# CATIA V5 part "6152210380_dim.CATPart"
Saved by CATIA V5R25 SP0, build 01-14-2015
Part number: 6152210380_dim
Source: made
Property "PROI_CREATED_ON": "12/17/2008 9:21:37 AM"
Property "BLANK_DRAWING": "--"
Property "DRAWN_BY": "FPA"
Property "FINISH": "--"
Property "HEAT_TREATMENT": "ASSIGN"
Property "MATERIAL": "ASSIGN"
Property "PROJECT": "--"
Property "PROTOTYPE_NO": "--"
Property "RELATED_DRAWING": "--"
Property "COMPLETE_MATERIAL": "ASSIGN-ASSIGN"
Property "DESCRIPTION": "Q-SHIELD 350-S"
Property "DRAWING_EXIST": "--"
Property "MANUFACTURER": "--"
Property "MANUFACTURER_2": "--"
Property "MANUFACTURER_REF": "--"
Property "TYPE_PART": "--"
Property "TODAY_DATE": "2021/06/09"
Property "PDMREV": "01.0"
Property "PDMRL": "Production"
Property "PROI_REVISION": "01"
Property "PROI_VERSION": "0"
Property "PROI_RELEASE": "Production"
Property "PTC_MODIFIED": false
Property "MFG_WP_MATERIAL": "ASSIGN"
Property "COMPANY_CODE": "---"
Property "DESCRIPTION_JP": "--"
Property "PQP_DOCUMENT": "--"
Property "GHOST": false
Property "NO_PART": false
Property "PTC_WM_ITERATION": "0"
Property "PTC_WM_VERSION": "01.0"
Property "PTC_WM_CREATED_ON": "09-Jun-21 09:10:23 AM"
Property "PTC_WM_MODIFIED_ON": "10-Jun-21 03:21:17 PM"
Property "PTC_WM_NAME": "6152210380_dim.prt"
Property "PTC_WM_NUMBER": "6152210380_DIM.PRT"
Property "PTC_WM_LIFECYCLE_STATE": "Production"
Property "PTC_WM_LIFECYCLE": "Design_Process"
Property "PTC_WM_REVISION": "01"
Property "PTC_WM_CREATED_BY": "Florian Pavageau (Grefpav) (Grefpav: CPD)"
Property "PTC_WM_MODIFIED_BY": "Florian Pavageau (Grefpav) (Grefpav: CPD)"
Property "PTC_ORGANIZATION_ID": "CPD"
Property "PTC_WM_LOCATION": "/Products/TORQUE MEASUREMENT SYSTEMS/A2010 - DELTAWRENCH GEN2/9-01-Dimensional D"
Property "PTC_WM_PART_NAME": "6152210380_dim.prt"
Property "PTC_WM_PART_NUMBER": "6152210380_DIM"
Property "PTC_WM_TEAM": "Default"
Property "EXPORT_CONTROL": "NULL"
Property "PTC_COMMON_NAME": "6152210380_dim.prt"
Property "PTC_MASTER_MATERIAL": "ASSIGN"
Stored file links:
  d:\ptc\Echange\temp\6152210380_dim.CATPart

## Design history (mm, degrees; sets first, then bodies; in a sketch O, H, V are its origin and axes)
AxisSystem1 "CS0": origin (0, 0, 0), X (1, 0, 0), Y (0, 1, 0), Z (0, 0, 1)
Set1
  DatumSurface1 "Sheet.1"
  DatumSurface2 "Sheet.2"
  DatumSurface3 "Sheet.3"
  DatumSurface4 "Sheet.4"
  DatumSurface5 "Sheet.5"
  DatumSurface6 "Sheet.6"
  DatumSurface7 "Sheet.7"
  DatumSurface8 "Sheet.8"
  DatumSurface9 "Sheet.9"
  DatumSurface10 "Sheet.10"
  DatumSurface11 "Sheet.11"
  DatumSurface12 "Sheet.12"
  DatumSurface13 "Sheet.13"
  DatumSurface14 "Sheet.14"
  DatumSurface15 "Sheet.15"
  DatumSurface16 "Sheet.16"
  DatumSurface17 "Sheet.17"
  DatumSurface18 "Sheet.18"
  DatumSurface19 "Sheet.19"
  DatumSurface20 "Sheet.20"
  DatumSurface21 "Sheet.21"
  DatumSurface22 "Sheet.22"
  DatumSurface23 "Sheet.23"
  DatumSurface24 "Sheet.24"
  DatumSurface25 "Sheet.25"
  DatumSurface26 "Sheet.26"
  DatumSurface27 "Sheet.27"
  DatumSurface28 "Sheet.28"
  DatumSurface29 "Sheet.29"
  DatumSurface30 "Sheet.30"
  DatumSurface31 "Sheet.31"
  DatumSurface32 "Sheet.32"
  DatumSurface33 "Sheet.33"
  DatumSurface34 "Sheet.34"
  DatumSurface35 "Sheet.35"
  DatumSurface36 "Sheet.36"
  DatumSurface37 "Sheet.37"
  DatumSurface38 "Sheet.38"
  DatumSurface39 "Sheet.39"
  DatumSurface40 "Sheet.40"
  DatumSurface41 "Sheet.41"
  DatumSurface42 "Sheet.42"
  DatumSurface43 "Sheet.43"
  DatumSurface44 "Sheet.44"
  DatumSurface45 "Sheet.45"
  DatumSurface46 "Sheet.46"
  DatumSurface47 "Sheet.47"
  DatumSurface48 "Sheet.48"
  DatumSurface49 "Sheet.49"
  DatumSurface50 "Sheet.50"
  DatumSurface51 "Sheet.51"
  DatumSurface52 "Sheet.52"
  DatumSurface53 "Sheet.53"
  DatumSurface54 "Sheet.54"
  DatumSurface55 "Sheet.55"
  DatumSurface56 "Sheet.56"
  DatumSurface57 "Sheet.57"
  DatumSurface58 "Sheet.58"
  DatumSurface59 "Sheet.59"
  DatumSurface60 "Sheet.60"
  DatumSurface61 "Sheet.61"
  DatumSurface62 "Sheet.62"
  DatumSurface63 "Sheet.63"
  DatumSurface64 "Sheet.64"
  DatumSurface65 "Sheet.65"
  DatumSurface66 "Sheet.66"
  DatumSurface67 "Sheet.67"
  DatumSurface68 "Sheet.68"
  DatumSurface69 "Sheet.69"
  DatumSurface70 "Sheet.70"
  DatumSurface71 "Sheet.71"
  DatumSurface72 "Sheet.72"
  DatumSurface73 "Sheet.73"
  DatumSurface74 "Sheet.74"
  DatumSurface75 "Sheet.75"
  DatumSurface76 "Sheet.76"
  DatumSurface77 "Sheet.77"
  DatumSurface78 "Sheet.78"
  DatumSurface79 "Sheet.79"
  DatumSurface80 "Sheet.80"
  DatumSurface81 "Sheet.81"
  DatumSurface82 "Sheet.82"
  DatumSurface83 "Sheet.83"
  DatumSurface84 "Sheet.84"
  DatumSurface85 "Sheet.85"
  DatumSurface86 "Sheet.86"
  DatumSurface87 "Sheet.87"
  DatumSurface88 "Sheet.88"
  DatumSurface89 "Sheet.89"
  DatumSurface90 "Sheet.90"
  DatumSurface91 "Sheet.91"
  DatumSurface92 "Sheet.92"
  DatumSurface93 "Sheet.93"
  DatumSurface94 "Sheet.94"
  DatumSurface95 "Sheet.95"
  DatumSurface96 "Sheet.96"
  DatumSurface97 "Sheet.97"
  DatumSurface98 "Sheet.98"
  DatumSurface99 "Sheet.99"
  DatumSurface100 "Sheet.100"
  DatumSurface101 "Sheet.101"
  DatumSurface102 "Sheet.102"
  DatumSurface103 "Sheet.103"
  DatumSurface104 "Sheet.104"
  DatumSurface105 "Sheet.105"
  DatumSurface106 "Sheet.106"
  DatumSurface107 "Sheet.107"
  DatumSurface108 "Sheet.108"
  DatumSurface109 "Sheet.109"
  DatumSurface110 "Sheet.110"
  DatumSurface111 "Sheet.111"
  DatumSurface112 "Sheet.112"
  DatumSurface113 "Sheet.113"
  DatumSurface114 "Sheet.114"
  DatumSurface115 "Sheet.115"
  DatumSurface116 "Sheet.116"
  DatumSurface117 "Sheet.117"
  DatumSurface118 "Sheet.118"
  DatumSurface119 "Sheet.119"
  DatumSurface120 "Sheet.120"
  DatumSurface121 "Sheet.121"
  DatumSurface122 "Sheet.122"
  DatumSurface123 "Sheet.123"
  DatumSurface124 "Sheet.124"
  DatumSurface125 "Sheet.125"
  DatumSurface126 "Sheet.126"
  DatumSurface127 "Sheet.127"
  DatumSurface128 "Sheet.128"
  DatumSurface129 "Sheet.129"
  DatumSurface130 "Sheet.130"
  DatumSurface131 "Sheet.131"
  DatumSurface132 "Sheet.132"
  DatumSurface133 "Sheet.133"
  DatumSurface134 "Sheet.134"
  DatumSurface135 "Sheet.135"
  DatumSurface136 "Sheet.136"
  DatumSurface137 "Sheet.137"
  DatumSurface138 "Sheet.138"
  DatumSurface139 "Sheet.139"
  DatumSurface140 "Sheet.140"
  DatumSurface141 "Sheet.141"
  DatumSurface142 "Sheet.142"
  DatumSurface143 "Sheet.143"
  DatumSurface144 "Sheet.144"
  DatumSurface145 "Sheet.145"
  DatumSurface146 "Sheet.146"
  DatumSurface147 "Sheet.147"
  DatumSurface148 "Sheet.148"
  DatumSurface149 "Sheet.149"
  DatumSurface150 "Sheet.150"
  DatumSurface151 "Sheet.151"
  DatumSurface152 "Sheet.152"
  DatumSurface153 "Sheet.153"
  DatumSurface154 "Sheet.154"
  DatumSurface155 "Sheet.155"
  DatumSurface156 "Sheet.156"
  DatumSurface157 "Sheet.157"
  DatumSurface158 "Sheet.158"
  DatumSurface159 "Sheet.159"
  DatumSurface160 "Sheet.160"
  DatumSurface161 "Sheet.161"
  DatumSurface162 "Sheet.162"
  DatumSurface163 "Sheet.163"
  DatumSurface164 "Sheet.164"
  DatumSurface165 "Sheet.165"
  DatumSurface166 "Sheet.166"
  DatumSurface167 "Sheet.167"
  DatumSurface168 "Sheet.168"
  DatumSurface169 "Sheet.169"
  DatumSurface170 "Sheet.170"
  DatumSurface171 "Sheet.171"
  DatumSurface172 "Sheet.172"
  DatumSurface173 "Sheet.173"
  DatumSurface174 "Sheet.174"
  DatumSurface175 "Sheet.175"
  DatumSurface176 "Sheet.176"
  DatumSurface177 "Sheet.177"
  DatumSurface178 "Sheet.178"
  DatumSurface179 "Sheet.179"
  DatumSurface180 "Sheet.180"
  DatumSurface181 "Sheet.181"
  DatumSurface182 "Sheet.182"
  DatumSurface183 "Sheet.183"
  DatumSurface184 "Sheet.184"
  DatumSurface185 "Sheet.185"
  DatumSurface186 "Sheet.186"
  DatumSurface187 "Sheet.187"
  DatumSurface188 "Sheet.188"
  DatumSurface189 "Sheet.189"
  DatumSurface190 "Sheet.190"
  DatumSurface191 "Sheet.191"
  DatumSurface192 "Sheet.192"
  DatumSurface193 "Sheet.193"
  DatumSurface194 "Sheet.194"
  DatumSurface195 "Sheet.195"
  DatumSurface196 "Sheet.196"
  DatumSurface197 "Sheet.197"
  DatumSurface198 "Sheet.198"
  DatumSurface199 "Sheet.199"
  DatumSurface200 "Sheet.200"
  DatumSurface201 "Sheet.201"
  DatumSurface202 "Sheet.202"
  DatumSurface203 "Sheet.203"
  DatumSurface204 "Sheet.204"
  DatumSurface205 "Sheet.205"
  DatumSurface206 "Sheet.206"
  DatumSurface207 "Sheet.207"
  DatumSurface208 "Sheet.208"
  DatumSurface209 "Sheet.209"
  DatumSurface210 "Sheet.210"
  DatumSurface211 "Sheet.211"
  DatumSurface212 "Sheet.212"
  DatumSurface213 "Sheet.213"
  DatumSurface214 "Sheet.214"
  DatumSurface215 "Sheet.215"
  DatumSurface216 "Sheet.216"
  DatumSurface217 "Sheet.217"
  DatumSurface218 "Sheet.218"
  DatumSurface219 "Sheet.219"
  DatumSurface220 "Sheet.220"
  DatumSurface221 "Sheet.221"
  DatumSurface222 "Sheet.222"
  DatumSurface223 "Sheet.223"
  DatumSurface224 "Sheet.224"
  DatumSurface225 "Sheet.225"
  DatumSurface226 "Sheet.226"
  DatumSurface227 "Sheet.227"
  DatumSurface228 "Sheet.228"
  DatumSurface229 "Sheet.229"
  DatumSurface230 "Sheet.230"
  DatumSurface231 "Sheet.231"
  DatumSurface232 "Sheet.232"
  DatumSurface233 "Sheet.233"
  DatumSurface234 "Sheet.234"
  DatumSurface235 "Sheet.235"
  DatumSurface236 "Sheet.236"
  DatumSurface237 "Sheet.237"
  DatumSurface238 "Sheet.238"
  DatumSurface239 "Sheet.239"
  DatumSurface240 "Sheet.240"
  DatumSurface241 "Sheet.241"
  DatumSurface242 "Sheet.242"
  DatumSurface243 "Sheet.243"
  DatumSurface244 "Sheet.244"
  DatumSurface245 "Sheet.245"
  DatumSurface246 "Sheet.246"
  DatumSurface247 "Sheet.247"
  DatumSurface248 "Sheet.248"
  DatumSurface249 "Sheet.249"
  DatumSurface250 "Sheet.250"
  DatumSurface251 "Sheet.251"
  DatumSurface252 "Sheet.252"
  DatumSurface253 "Sheet.253"
  DatumSurface254 "Sheet.254"
  DatumSurface255 "Sheet.255"
  DatumSurface256 "Sheet.256"
  DatumSurface257 "Sheet.257"
  DatumSurface258 "Sheet.258"
  DatumSurface259 "Sheet.259"
  DatumSurface260 "Sheet.260"
  DatumSurface261 "Sheet.261"
  DatumSurface262 "Sheet.262"
  DatumSurface263 "Sheet.263"
  DatumSurface264 "Sheet.264"
  DatumSurface265 "Sheet.265"
  DatumSurface266 "Sheet.266"
  DatumSurface267 "Sheet.267"
  DatumSurface268 "Sheet.268"
  DatumSurface269 "Sheet.269"
  DatumSurface270 "Sheet.270"
  DatumSurface271 "Sheet.271"
  DatumSurface272 "Sheet.272"
  DatumSurface273 "Sheet.273"
  DatumSurface274 "Sheet.274"
  DatumSurface275 "Sheet.275"
  DatumSurface276 "Sheet.276"
  DatumSurface277 "Sheet.277"
  DatumSurface278 "Sheet.278"
  DatumSurface279 "Sheet.279"
  DatumSurface280 "Sheet.280"
  DatumSurface281 "Sheet.281"
  DatumSurface282 "Sheet.282"
  DatumSurface283 "Sheet.283"
  DatumSurface284 "Sheet.284"
  DatumSurface285 "Sheet.285"
  DatumSurface286 "Sheet.286"
  DatumSurface287 "Sheet.287"
  DatumSurface288 "Sheet.288"
  DatumSurface289 "Sheet.289"
  DatumSurface290 "Sheet.290"
  DatumSurface291 "Sheet.291"
  DatumSurface292 "Sheet.292"
  DatumSurface293 "Sheet.293"
  DatumSurface294 "Sheet.294"
  DatumSurface295 "Sheet.295"
  DatumSurface296 "Sheet.296"
  DatumSurface297 "Sheet.297"
  DatumSurface298 "Sheet.298"
  DatumSurface299 "Sheet.299"
  DatumSurface300 "Sheet.300"
  DatumSurface301 "Sheet.301"
  DatumSurface302 "Sheet.302"
  DatumSurface303 "Sheet.303"
  DatumSurface304 "Sheet.304"
  DatumSurface305 "Sheet.305"
  DatumSurface306 "Sheet.306"
  DatumSurface307 "Sheet.307"
  DatumSurface308 "Sheet.308"
  DatumSurface309 "Sheet.309"
  DatumSurface310 "Sheet.310"
  DatumSurface311 "Sheet.311"
  DatumSurface312 "Sheet.312"
  DatumSurface313 "Sheet.313"
  DatumSurface314 "Sheet.314"
  DatumSurface315 "Sheet.315"
  DatumSurface316 "Sheet.316"
  DatumSurface317 "Sheet.317"
  Plane1 "RIGHT": stored without definition
  Plane2 "TOP": stored without definition
  Plane3 "FRONT": stored without definition
Body1 "PartBody" (main body)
